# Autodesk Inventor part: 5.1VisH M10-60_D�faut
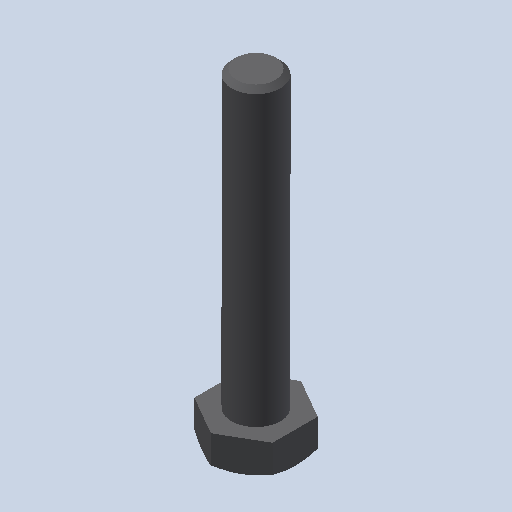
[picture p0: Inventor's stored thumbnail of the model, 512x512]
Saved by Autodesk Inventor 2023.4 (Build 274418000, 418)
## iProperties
Created: 2011-01
Part Number: 5.1VisH M10-60_D�faut
Document SubType Name: Modeling
Designer: eric
Density: 1 g/cm^3
Mass: 6.11218 g
Surface Area: 26.5299 cm^2
Volume: 6.11218 cm^3
Material: Générique
Appearance: Red
Author: eric
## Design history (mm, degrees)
feature "Base1"
node "Corps solides"
node "Corps surfaciques"
node "Solide1"
